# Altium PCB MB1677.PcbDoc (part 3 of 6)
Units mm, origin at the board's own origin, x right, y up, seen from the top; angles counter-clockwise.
Board outline 78 x 105 mm, 6 copper layers (Top Layer, Signal Layer 1, Signal Layer 2, Signal Layer 3, Signal Layer 4, Bottom Layer), stack 1.574 mm thick; 404 components, 325 nets, 1691 pads, 961 vias.
Unrouted connection lines stored in the file: 9.
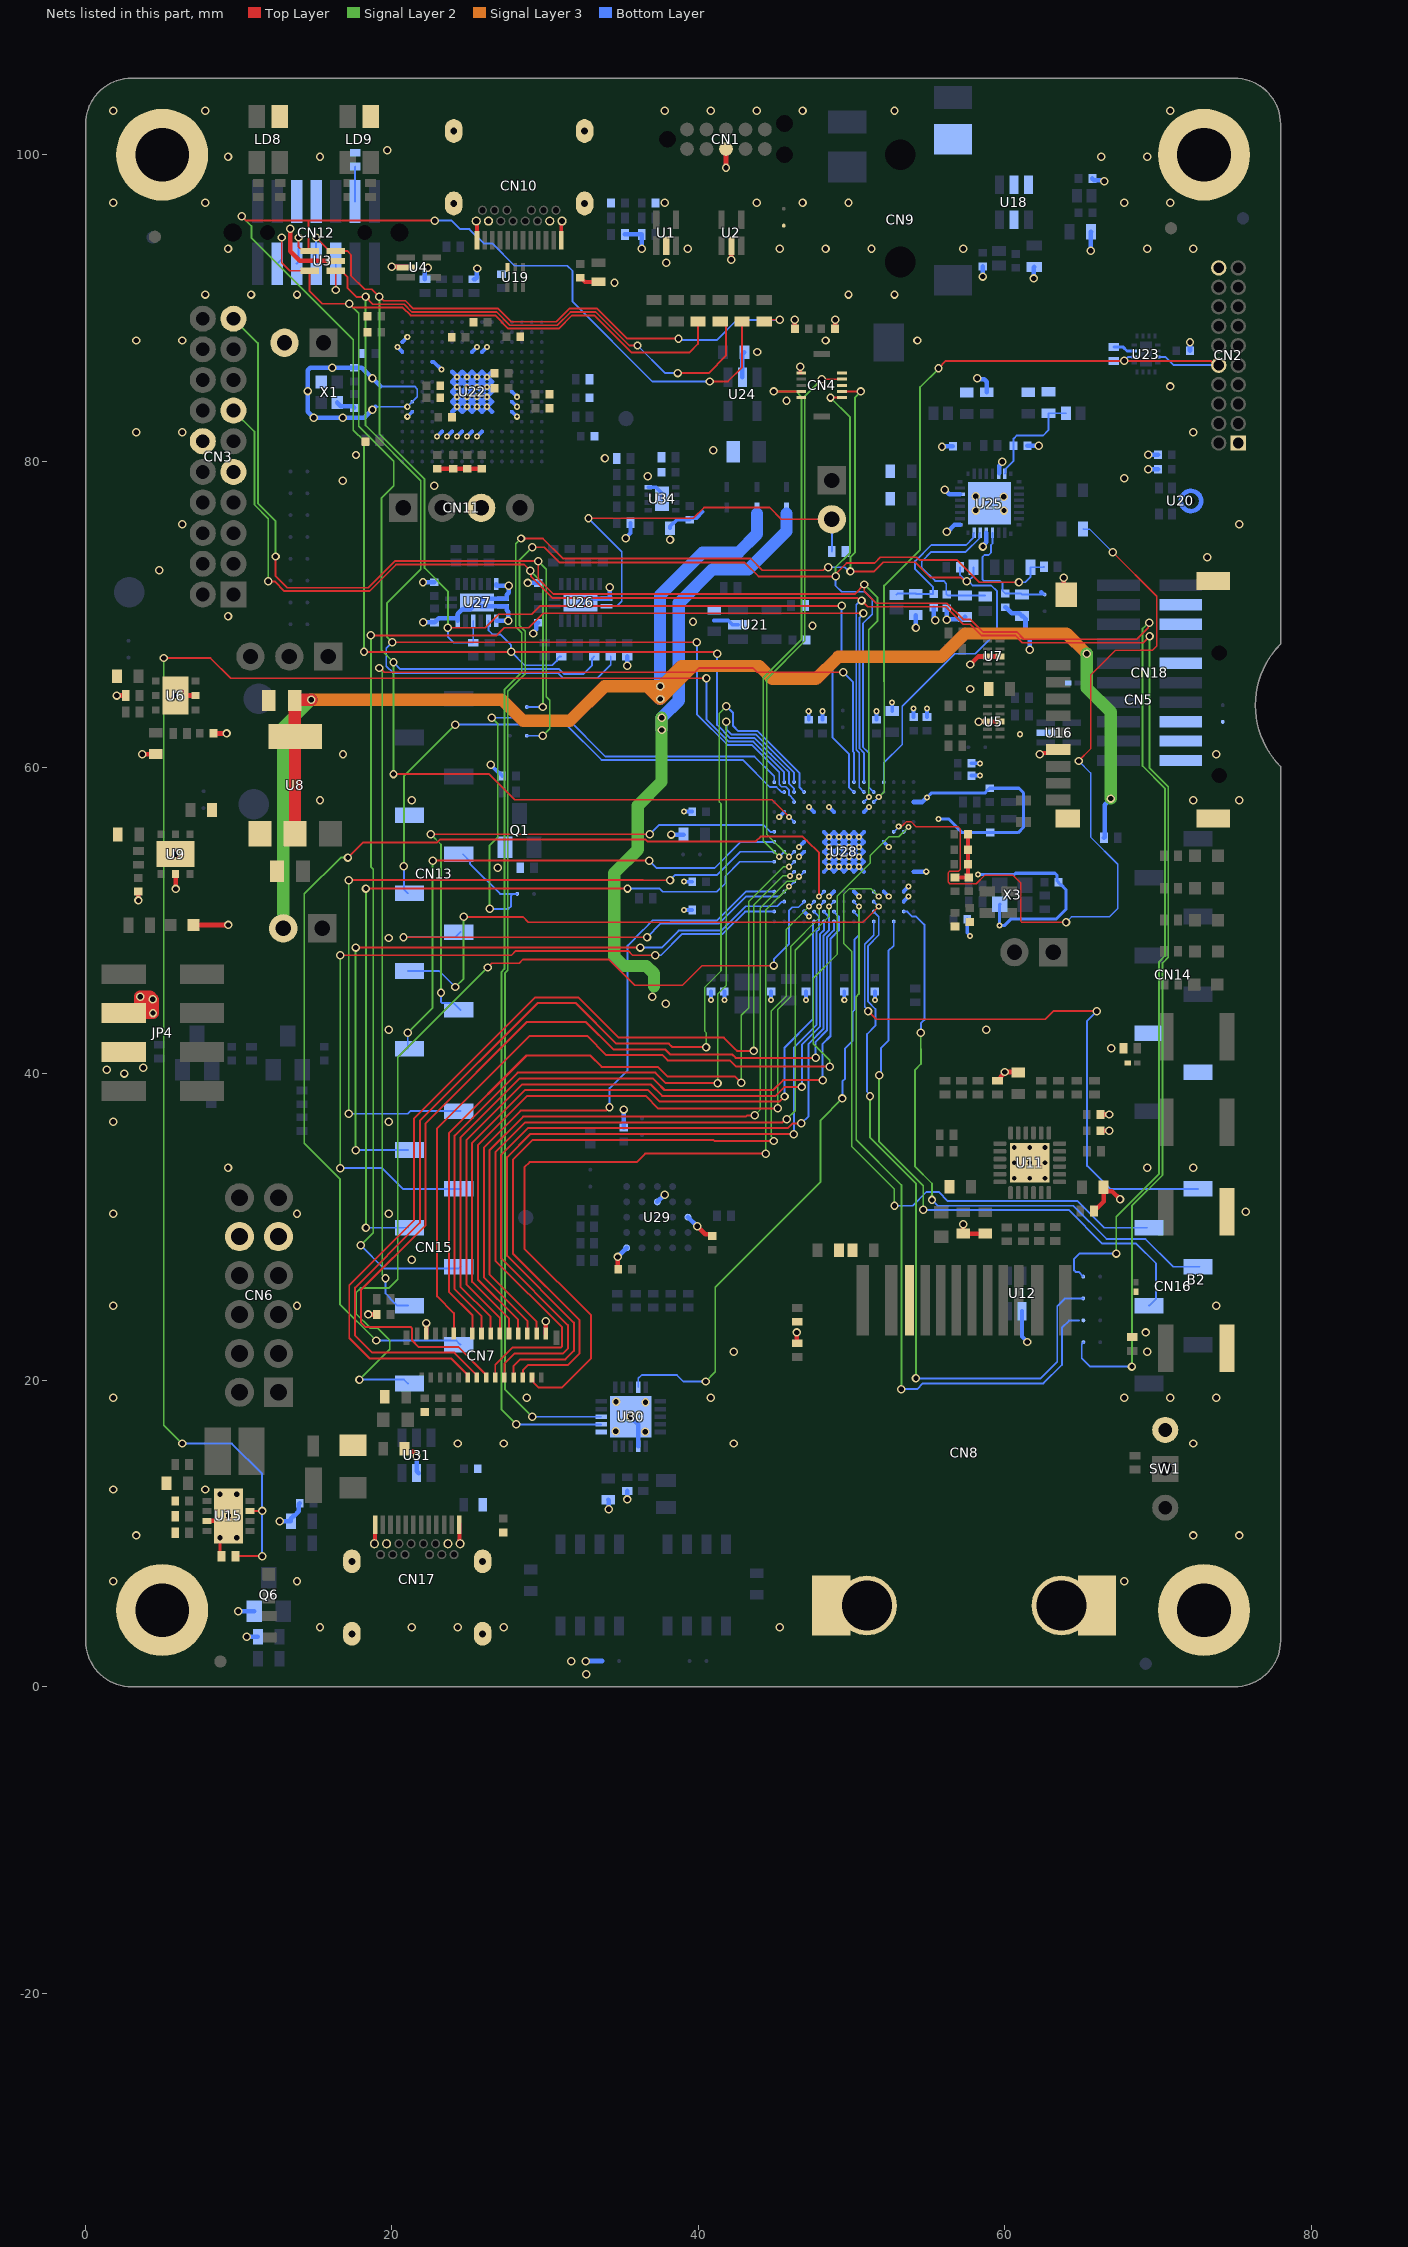
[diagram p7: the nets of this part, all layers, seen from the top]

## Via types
v1: diameter 0.55, hole 0.35, Top Layer to Bottom Layer, tented both sides, 748 vias
v2: diameter 0.4, hole 0.2, Top Layer to Bottom Layer, tented both sides, 203 vias
v3: diameter 0.6, hole 0.3, Top Layer to Bottom Layer, tented both sides, 9 vias
v4: diameter 0.55, hole 0.33, Top Layer to Bottom Layer, tented both sides, 1 vias

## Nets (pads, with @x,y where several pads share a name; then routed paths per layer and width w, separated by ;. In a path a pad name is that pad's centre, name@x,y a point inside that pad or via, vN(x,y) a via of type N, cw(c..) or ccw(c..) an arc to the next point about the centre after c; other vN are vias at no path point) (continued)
5V_UCPD: D4.1 JP4.3 SB29.1 | length 47.8
  Top Layer w0.8: JP4.3@2.5,43.965 JP4.3@2.51,43.975 ; JP4.3@2.51,43.975 JP4.3@3.31,43.975 ; JP4.3@2.51,43.975 2.75,44.215 JP4.3@3.55,44.215 ; JP4.3@3.31,43.975 v1(4.4,43.975) 4.4,44.85 v1(4.375,44.875) ; JP4.3@3.31,43.975 JP4.3@3.55,44.215 ; JP4.3@3.55,44.215 3.715,44.215 v1(4.375,44.875) ; JP4.3@3.55,44.215 3.55,45.015 3.575,45.04 v1(3.575,45.05) 4.2,45.05 v1(4.375,44.875)
  Signal Layer 2 w0.8: 37.1,45.725 37.1,46.55 36.6,47.05 35.125,47.05 34.5,47.675 34.5,53.1 36.05,54.65 36.05,57.525 37.6,59.075 v1(37.6,62.45) v1(37.6,63.25)
  Bottom Layer w0.3: v1(32.65,1.675) 32.655,1.68 SB29.1@33.725,1.68
  Bottom Layer w0.8: v1(37.6,62.45) v1(37.6,63.25) 38.725,64.375 38.725,70.75 40.9,72.925 43.25,72.925 45.75,75.425 45.75,76.58
  other v1: 32.675,0.825 31.7,1.675 37.875,44.575 37,45.05
5V_VIN: C24.2 D3.1 JP3.2 JP4.5 R90.2 U8.2 U8.4 | length 114.3
  Top Layer w0.8: U8.2@13.675,55.675 U8.4@13.675,62.025 13.65,62.05 C24.2@13.65,64.375 13.7,64.425 v1(14.725,64.425)
  Signal Layer 2 w0.8: JP3.2@12.905,49.5 12.905,62.605 v1(14.725,64.425) ; v1(65.35,67.425) 65.35,65.2 66.925,63.625 v1(66.925,57.975)
  Signal Layer 3 w0.8: v1(14.725,64.425) 27.175,64.425 28.55,63.05 31.625,63.05 33.875,65.3 36.675,65.3 ; v1(65.35,67.425) 64.025,68.75 57.4,68.75 55.875,67.225 49.125,67.225 47.675,65.775 44.825,65.775 44.3,66.3 43.975,66.625 39.65,66.625 ; 36.675,65.3 v1(37.5,65.3) ; 36.675,65.3 v1(37.5,64.475) ; v1(37.5,64.475) v1(37.5,65.3) ; v1(37.5,64.475) 39.65,66.625 ; v1(37.5,65.3) 37.575,65.3 38.9,66.625 39.65,66.625
  Bottom Layer w0.3: R90.2@66.475,55.41 66.513,55.448 66.513,57.563 v1(66.925,57.975)
  Bottom Layer w0.8: v1(37.5,64.475) v1(37.5,65.3) 37.5,71.25 40.275,74.025 42.6,74.025 43.825,75.25 43.825,76.58
  other v1: 2.525,40.025 1.375,40.275 3.775,40.4
ARD_A0: CN16.6 U28.R5 | length 39.8
  Top Layer w0.12: v1(51.075,44.1) 51.6,43.575 62.65,43.575 63.175,44.1 v1(66,44.1)
  Bottom Layer w0.12: v1(51.075,44.1) 51.075,44.164 50.855,44.384 50.855,48.462 51.45,49.057 U28.R5@51.45,49.95 ; v1(66,44.1) 65.375,43.475 65.375,34 66.88,32.495 CN16.6@72.615,32.495
ARD_A1: CN16.5 U28.M5 | length 42.7
  Signal Layer 2 w0.1: v2(51.775,51.575) 51.25,52.1 49.855,52.1 49.475,51.72 49.475,51.625 49.475,48.525 50.025,47.975 50.025,35.25 52.8,32.475 v1(52.8,31.4)
  Bottom Layer w0.12: v1(52.8,31.4) 53.991,31.4 54.891,32.3 55.675,32.3 56.275,31.7 64.76,31.7 66.505,29.955 CN16.5@69.298,29.955
  Bottom Layer w0.13: U28.M5@51.45,51.9 v2(51.775,51.575)
ARD_A2: CN16.4 U28.P2 | length 39.7
  Signal Layer 2 w0.1: 54.525,41.625 v1(54.525,42.7)
  Signal Layer 2 w0.12: 54.525,41.625 54.525,40.65 54.15,40.275 54.15,33.95 55.25,32.85 v1(55.25,31.775)
  Bottom Layer w0.12: U28.P2@53.4,50.6 53.647,50.6 53.972,50.275 54.225,50.275 54.75,49.75 54.75,43.525 54.525,43.3 v1(54.525,42.7) ; v1(55.25,31.775) 55.625,31.4 64.47,31.4 66.645,29.225 69.175,29.225 70.985,27.415 CN16.4@72.727,27.415
ARD_A3: CN16.3 U28.R3 | length 40
  Signal Layer 2 w0.12: v1(51.8,39.925) 51.8,35.575 54.675,32.7 v1(54.675,31.125)
  Bottom Layer w0.12: v1(51.8,39.925) 51.925,40.05 51.925,41.7 52.405,42.18 52.405,48.033 52.75,48.378 U28.R3@52.75,49.95 ; v1(54.675,31.125) 64.175,31.125 66.375,28.925 68.575,28.925 69.875,27.625 69.875,25.325 69.425,24.875 CN16.3@69.41,24.875
ARD_A4: SB24.1 U28.P5 | length 47.9
  Signal Layer 2 w0.12: v1(51.2,38.55) 51.2,35.864 54.2,32.864 v1(54.2,20.125)
  Bottom Layer w0.12: v1(51.2,38.55) 51.2,38.64 51.005,38.835 51.005,42.605 51.55,43.15 51.55,44.24 51.075,44.715 51.075,48.371 51.775,49.071 51.775,50.275 U28.P5@51.45,50.6 ; v1(54.2,20.125) 62.35,20.125 63.425,21.2 63.425,24.825 63.95,25.35 SB24.1@65.125,25.35
ARD_A5: SB23.1 U28.N7 | length 48.1
  Signal Layer 2 w0.12: v2(50.475,50.925) 50.475,45.225 50.3,45.05 50.3,35.7 53.25,32.75 v1(53.25,19.425)
  Bottom Layer w0.12: v1(53.25,19.425) 54.275,19.425 54.65,19.8 62.525,19.8 63.725,21 63.725,23.425 64.2,23.9 64.85,23.9
  Bottom Layer w0.13: U28.N7@50.15,51.25 v2(50.475,50.925)
ARD_D0: CN15.1 U28.N12 | length 62.2
  Top Layer w0.1: 36.4,45.79 38.965,45.79 40.25,47.075 v1(44.925,47.075)
  Top Layer w0.12: v1(26.25,46.95) 26.525,47.225 28.3,47.225 28.55,47.475 34.15,47.475 35.835,45.79 36.4,45.79
  Signal Layer 2 w0.12: v1(17.875,20.05) 19.85,22.025 19.85,22.625 19.05,23.425 18.575,23.425 17.65,24.35 17.65,25.725 17.95,26.025 19.8,26.025 20.375,26.6 20.375,41.075 v1(26.25,46.95)
  Bottom Layer w0.12: v1(17.875,20.05) 20.783,20.05 CN15.1@21.038,19.795 ; v1(44.925,47.075) 44.925,47.5 45.925,48.5 45.925,50.678 46.132,50.885 46.535,50.885 U28.N12@46.9,51.25
ARD_D1: CN15.2 U28.M10 | length 75.7
  Top Layer w0.13: v1(17.125,54.125) 18.1,55.1 22.925,55.1 23.125,55.3 36.55,55.3 36.675,55.175 43.75,55.175 44.07,55.495 46.805,55.495 47.075,55.225 47.875,54.425 v2(47.875,51.575)
  Signal Layer 2 w0.12: v1(17.125,54.125) 16.65,54.125 14.275,51.75 14.275,35.475 16.6,33.15 16.6,24.975 v1(18.975,22.6)
  Bottom Layer w0.12: v1(18.975,22.6) 24.202,22.6 CN15.2@24.467,22.335
  Bottom Layer w0.13: v2(47.875,51.575) U28.M10@48.2,51.9
ARD_D2: CN15.3 U28.A7 | length 80.9
  Top Layer w0.12: v1(19.175,66.5) 19.22,66.5 19.256,66.464 19.505,66.215 39.76,66.215 40.045,66.5 43.55,66.5 43.825,66.225 v1(49.45,66.225)
  Signal Layer 2 w0.12: v1(19.175,66.5) 19.365,66.31 19.365,26.885 v1(19.575,26.675)
  Bottom Layer w0.12: v1(19.575,26.675) 19.575,25.675 19.891,25.359 19.891,25.323 20.339,24.875 CN15.3@21.038,24.875 ; v1(49.45,66.225) 50.085,65.59 50.085,61.059 50.15,60.994 50.15,60.575 U28.A7@50.15,59.05
ARD_D3: CN15.4 U28.A6 | length 91.4
  Top Layer w0.12: v1(18.625,68.625) 26.825,68.625 27.325,69.125 28.925,69.125 29.875,70.075 v1(50.775,70.075)
  Signal Layer 2 w0.12: v1(17.958,28.808) 18.775,29.625 18.775,53.375 18.625,53.525 v1(18.625,68.625)
  Bottom Layer w0.12: v1(17.958,28.808) 19.465,27.3 24.352,27.3 CN15.4@24.467,27.415 ; v1(50.775,70.075) 50.775,70.04 50.525,69.79 50.525,65.625 50.525,61.242 50.8,60.967 U28.A6@50.8,59.05
ARD_D4: CN15.5 U28.J15 | length 52.7
  Top Layer w0.12: v1(18.3,52.1) v1(35.375,52.1)
  Signal Layer 2 w0.12: v1(18.3,29.95) v1(18.3,52.1)
  Bottom Layer w0.12: v1(18.3,29.95) 18.305,29.955 CN15.5@21.038,29.955 ; v1(35.375,52.1) 37.465,52.1 37.675,51.89 41.21,51.89 41.77,52.45 41.77,52.907 42.713,53.85 43.05,53.85 U28.J15@44.95,53.85
ARD_D5: CN15.6 U28.P15 | length 52
  Top Layer w0.12: v1(16.625,47.75) 27.8,47.75 28.08,48.03 35.42,48.03 35.7,47.75 v1(37.175,47.75)
  Signal Layer 2 w0.12: v1(16.625,33.85) v1(16.625,47.75)
  Bottom Layer w0.12: v1(16.625,33.85) 19.35,33.85 20.705,32.495 CN15.6@24.467,32.495 ; v1(37.175,47.75) 37.56,47.75 38.95,49.14 41.592,49.14 43.052,50.6 U28.P15@44.95,50.6
ARD_D6: CN15.7 U28.N14 | length 45.9
  Top Layer w0.12: v1(17.625,48.25) v1(36.2,48.25)
  Signal Layer 2 w0.12: v1(17.625,35.025) v1(17.625,48.25)
  Bottom Layer w0.12: v1(17.625,35.025) 21.028,35.025 CN15.7@21.038,35.035 ; v1(36.2,48.25) 37.6,48.25 38.71,49.36 41.5,49.36 43.09,50.95 45.15,50.95 45.429,51.229 45.579,51.229 U28.N14@45.6,51.25
ARD_D7: CN15.8 U28.H15 | length 51.2
  Top Layer w0.1: 36.4,52.65 v1(38.15,52.65)
  Top Layer w0.12: v1(17.175,52.65) 36.4,52.65
  Signal Layer 2 w0.12: v1(17.175,37.4) v1(17.175,52.65)
  Bottom Layer w0.12: v1(17.175,37.4) 21.025,37.4 21.2,37.575 CN15.8@24.466,37.575 ; v1(38.15,52.65) 38.495,52.995 41.235,52.995 42.74,54.5 U28.H15@44.95,54.5
ARD_D8: CN13.1 U28.G15 | length 36.2
  Top Layer w0.12: v1(22.65,53.925) v1(36.8,53.925)
  Signal Layer 2 w0.12: v1(21.025,42.7) 22.65,44.325 v1(22.65,53.925)
  Bottom Layer w0.12: v1(21.025,42.7) 21.025,41.652 CN13.1@21.038,41.639 ; v1(36.8,53.925) 37.29,53.435 41.053,53.435 42.768,55.15 43.2,55.15 U28.G15@44.95,55.15
ARD_D9: CN13.2 U28.F15 | length 35.6
  Top Layer w0.12: v1(22.525,55.65) v1(36.825,55.65)
  Signal Layer 2 w0.12: v1(22.525,55.65) 23.2,54.975 v1(23.2,45.3)
  Bottom Layer w0.12: v1(23.2,45.3) 23.2,44.7 23.273,44.627 24.019,44.627 CN13.2@24.467,44.179 ; v1(36.825,55.65) 37.42,56.245 44.255,56.245 44.7,55.8 U28.F15@44.95,55.8
ARD_D10: CN13.3 U28.N5 | length 36.5
  Top Layer w0.1: 36.4,49.9 50.75,49.9 v2(51.775,50.925)
  Top Layer w0.12: v1(24.675,50.25) 28.55,50.25 28.9,49.9 36.4,49.9
  Signal Layer 2 w0.12: v1(24.125,45.675) 24.675,46.225 v1(24.675,50.25)
  Bottom Layer w0.12: CN13.3@21.038,46.719 23.081,46.719 v1(24.125,45.675)
  Bottom Layer w0.13: U28.N5@51.45,51.25 v2(51.775,50.925)
ARD_D11: CN13.4 U28.M14 | length 29.9
  Top Layer w0.1: v1@36.4,48.925 v1(36.65,48.925)
  Top Layer w0.12: v1(20.75,48.925) v1@36.4,48.925
  Bottom Layer w0.12: v1(20.75,48.925) 24.133,48.925 CN13.4@24.467,49.259 ; v1(36.65,48.925) 37.525,49.8 41.318,49.8 43.093,51.575 45.275,51.575 U28.M14@45.6,51.9
ARD_D12: CN13.5 U28.B14 | length 35.8
  Signal Layer 2 w0.12: v1(20.775,53.55) 20.775,59.442 v1(24.133,62.8)
  Bottom Layer w0.12: v1(20.775,53.55) 20.775,52.062 CN13.5@21.038,51.799 ; v1(24.133,62.8) 31.375,62.8 33.675,60.5 42.9,60.5 44.675,58.725 45.1,58.725 45.417,58.408 45.592,58.408 U28.B14@45.6,58.4
ARD_D13: CN13.6 SB15.1 U28.A15 | length 40.3
  Signal Layer 2 w0.12: v1(26.375,50.775) 26.375,54.925 26.9,55.45 26.9,62.85 v1(26.5,63.25)
  Bottom Layer w0.12: CN13.6@24.637,54.339 25.085,53.891 25.085,53.721 27.056,51.75 27.9,51.75 ; v1(26.375,50.775) 27.6,50.775 27.775,50.95 27.775,51.625 27.9,51.75 ; v1(26.5,63.25) 31.395,63.25 33.925,60.72 43.655,60.72 44.95,59.425 U28.A15@44.95,59.05 ; SB15.1@28.175,51.75 27.9,51.75
Audio_INT: R57.1 U28.F3 | length 55
  Top Layer w0.1: v2(53.075,56.15) 53.129,56.204 53.316,56.204 53.375,56.262 53.375,56.27 53.58,56.475 53.87,56.475 54.195,56.15 56.947,56.15 57.105,55.992 57.105,53.358 56.977,53.23 56.946,53.23 56.408,53.23 56.32,53.142 56.32,52.508 56.408,52.42 58.14,52.42 58.7,52.98 60.52,52.98 61.05,52.45 61.05,49.959 61.109,49.9 v1(64,49.9) ; v1(64.825,60.425) 64.825,60.443 65.6,61.218 65.6,66.025 67.225,67.65 69.65,67.65 69.925,67.925 69.925,71.175 v1(67.057,74.043)
  Bottom Layer w0.1: U28.F3@52.75,55.8 53.025,56.075 v2@53.05,56.1 ; v1(64,49.9) 64.35,50.25 66.825,50.25 67.375,50.8 67.375,53.693 65.6,55.468 65.6,59.65 v1(64.825,60.425) ; R57.1@65.125,75.575 65.136,75.564 65.536,75.564 v1(67.057,74.043)
AVDD: C126.2 C127.2 L8.2 U25.23 | length 7.3
  Bottom Layer w0.12: U25.23@60,79.175 60.05,79.225 60.05,79.5 60.575,80.025 60.575,81.475 60.775,81.675 62.5,81.675 62.85,82.025 C126.2@62.85,83.125 L8.2@64,83.125
CPVDD: C74.2 C75.2 L7.2 U25.7 | length 9.9
  Bottom Layer w0.12: L7.2@52.925,71.275 53,71.35 C74.2@54.2,71.35 54.225,71.325 55.325,71.325 55.325,71.775 54.15,72.95 54.15,73.475 55.2,74.525 57.475,74.525 57.95,75 57.95,75.275 U25.7@58,75.325
DBVDD: C56.2 C58.2 SB1.2 U25.4 | length 8.3
  Bottom Layer w0.12: U25.4@59.2,75.325 59.2,74.625 59.1,74.525 59.1,74.025 58.95,73.875 58.675,73.875 58.55,73.75 58.55,72.264 58.62,72.193 59.674,72.193 59.85,72.018 59.85,71.535 C58.2@60.025,71.36 61.055,71.36 C56.2@61.125,71.29 ; C56.2@61.135,71.3 SB1.2@62.6,71.3
  Bottom Layer w0.3: 62.385,71.44 62.425,71.4
DCVDD: C88.2 C89.2 L6.2 U25.6 | length 10.4
  Bottom Layer w0.12: C89.2@56.2,71.3 56.181,71.319 56.181,72.003 56.006,72.178 55.447,72.178 54.575,73.05 54.575,73.45 55.2,74.075 57.45,74.075 58.35,74.975 58.35,75.275 U25.6@58.4,75.325 ; C89.2@56.275,71.225 C88.2@57.4,71.225 L6.2@58.725,71.225
DETECTn: CN2.10 R70.2 U23.3 U23.10 U28.C5 | length 54.3
  Top Layer w0.12: v1(55.675,86.075) 56.144,86.544 v1(67.794,86.544) 73.455,86.544 73.733,86.265 CN2.10@73.965,86.265
  Signal Layer 2 w0.1: v2(51.775,58.075) 52.125,58.425 52.125,65.625
  Signal Layer 2 w0.12: 52.125,65.625 52.125,71.875 54.475,74.225 54.475,84.84 55.675,86.04 v1(55.675,86.075)
  Bottom Layer w0.12: R70.2@67.116,86.544 v1(67.794,86.544) 68.044,86.794 U23.10@68.441,86.794 ; U23.3@69.991,86.794 70.506,86.794 71.035,86.265 CN2.10@73.965,86.265
  Bottom Layer w0.13: U28.C5@51.45,57.75 v2(51.775,58.075)
GND: B2.1 B2.2 C1.2 C2.2 C3.1 C4.1 C5.2 C6.2 C7.2 C8.2 C9.2 C10.2 C11.2 C12.2 C13.2 C14.2 C15.2 C16.2 C17.2 C18.2 C19.2 C20.2 C21.2 C22.1 C23.2 C24.1 C25.2 C26.1 C27.1 C28.1 C29.2 C30.2 C31.2 C32.1 C33.1 C34.1 C35.1 C36.1 C37.1 C38.1 C39.1 C40.2 C41.1 C42.1 C43.1 C44.1 C45.1 C46.1 C47.1 C48.2 C49.1 C50.2 C51.1 C52.1 C53.1 C54.2 C55.1 C56.1 C57.2 C58.1 C59.1 C60.1 C61.1 C62.2 C63.1 C64.1 C65.1 C66.1 C67.1 C68.1 C69.1 C70.1 C71.1 C72.2 C73.1 C74.1 C75.1 C77.1 C78.1 C79.2 C80.1 C81.1 C83.1 C84.1 C88.1 C89.1 C90.1 C91.2 C92.1 C93.2 C94.1 C95.2 C96.1 C97.2 C98.2 C99.2 C100.1 C101.1 C102.1 C103.2 C104.1 C105.1 C106.2 C107.1 C108.2 C109.1 C110.2 C111.2 C112.2 C113.1 C114.1 C115.1 C116.2 C119.1 C120.1 C121.2 C122.1 C123.1 C126.1 C127.1 C128.1 C129.1 CN1.3 CN2.1 CN2.20 CN3.5 CN3.16 CN4.1 CN4.3 CN4.6 CN4.10 CN5.6 CN5.10 CN5.11 CN5.12 CN5.13 CN6.5 CN6.11 CN7.1 CN7.27 CN8.10 CN8.13 CN8.14 CN9.3 CN10.A1 CN10.A12 CN10.B1 CN10.B12 CN10.SH1 CN10.SH2 CN10.SH3 CN10.SH4 CN11.3 CN12.5 CN12.7 CN13.7 CN14.2 CN14.3 CN17.A1 CN17.A12 CN17.B1 CN17.B12 CN17.SH1 CN17.SH2 CN17.SH3 CN17.SH4 CN18.3 CN18.5 CN18.9 CN18.15 CN18.17 CN18.19 H1.1 H2.1 H3.1 H4.1 JP5.2 LD5.2 LD8.3 LD9.3 Q1.2 Q6.2 R14.1 R29.2 R36.1 R40.2 R45.2 R48.2 R50.1 R51.1 R52.1 R53.1 R54.1 R55.1 R58.1 R65.2 R67.2 R70.1 R71.2 R74.1 R77.1 R79.1 R91.1 R123.2 R124.1 R126.2 R129.2 R132.1 R133.1 R137.1 R139.1 SB17.1 SB18.1 SW1.3 U1.2 U2.2 U3.2 U4.2 U5.3 U5.8 U6.2 U6.EP U7.3 U7.8 U8.1 U9.2 U9.EP U10.2 U11.EP U12.2 U13.2 U14.2 U15.3 U15.9 U16.2 U17.2 U18.2 U18.3 U18.5 U19.3 U20.3 U21.2 U22.D5 U22.D6 U22.D7 U22.D8 U22.D9 U22.F2 U22.F6 U22.F7 U22.F8 U22.F9 U22.F10 U22.F12 U22.G2 U22.G6 U22.G7 U22.G8 U22.G9 U22.G10 U22.G12 U22.H6 U22.H7 U22.H8 U22.H9 U22.H10 U22.H12 U22.J6 U22.J7 U22.J8 U22.J9 U22.J10 U22.K6 U22.K7 U22.K8 U22.K9 U22.K10 U22.L4 U22.M1 U22.M8 U22.M9 U22.N1 U23.11 U24.2 U25.5 U25.9 U25.14 U25.22 U25.33 U26.8 U26.17 U27.7 U27.8 U27.9 U27.10 U27.15 U27.17 U28.C1 U28.D6 U28.D9 U28.D11 U28.D14 U28.F6 U28.F7 U28.F8 U28.F9 U28.F10 U28.G4 U28.G6 U28.G7 U28.G8 U28.G9 U28.G10 U28.G12 U28.H6 U28.H7 U28.H8 U28.H9 U28.H10 U28.H12 U28.J6 U28.J7 U28.J8 U28.J9 U28.J10 U28.K1 U28.K6 U28.K7 U28.K8 U28.K9 U28.K10 U28.M2 U28.M4 U28.M7 U28.M9 U28.N2 U28.P12 U29.B3 U29.C1 U29.E5 U30.12 U30.16 U30.21 U31.2 U32.2 U34.8 U34.9 X1.2 X1.4 X3.2 | length 253.9
  Top Layer w0.2: v1(8.775,9.725) 8.775,8.625 R55.1@8.875,8.525 ; v1(46.65,86.15) 46.65,85.75 CN4.10@46.725,85.75
  Top Layer w0.25: CN17.B12@18.85,9.335 18.9,9.385 CN17.A1@18.9,10.585 ; CN17.A12@24.4,10.585 24.4,9.385 CN17.B1@24.45,9.335 ; CN10.B1@25.5,95.67 25.55,95.62 CN10.A12@25.55,94.42 ; CN10.A1@31.05,94.42 31.05,95.62 CN10.B12@31.1,95.67 ; C57.2@32.3,91.975 32.325,91.975 32.6,91.7 U13.2@33.475,91.7 ; C55.1@56.75,52.825 C33.1@57.65,52.825 57.6,52.875 C31.2@57.6,53.7 C30.2@57.6,54.625 C29.2@57.6,55.65 ; v1(58.3,63) U5.8@59.685,63 U5.3@58.865,63 ; v1(62.275,60.875) 62.356,60.875 62.431,60.95 63.275,60.95 CN5.6@63.5,61.175
  Top Layer w0.3: v1(2.025,64.7) R14.1@2.625,64.7 ; v1(3.45,51.325) C34.1@3.45,51.9 ; v1(3.7,60.875) C25.2@4.575,60.875 ; v1(5.875,52.075) U9.2@5.875,53.05 ; v1(5.875,64.7) U6.2@7.175,64.7 ; LD5.2@7.048,49.725 v1(9.3,49.725) v1@9.325,49.75 ; U15.3@7.925,10.825 9,10.825 v1(9.325,11.15) ; C26.1@8.35,62.225 v1(9.2,62.225) ; v1(13.35,95.175) 13.35,93.7 13.975,93.075 U3.2@16.325,93.075 ; v1(18.45,24.3) C48.2@19,24.3 ; v1(19.976,92.68) 20.995,92.68 U4.2@21.025,92.65 ; C52.1@20.825,15.525 20.994,15.356 21.419,15.356 21.625,15.15 v1(21.625,15.05) ; CN7.27@22.24,23.05 v1(22.24,23.74) ; C16.2@22.95,79.5 C17.2@24,79.5 C18.2@24.925,79.5 C19.2@25.85,79.5 ; CN7.1@30.04,23.05 v1(30.04,23.86) ; v1(34.725,28.055) 34.725,27.3 C47.1@34.775,27.25 ; v1(39.915,30.055) 40.44,29.53 40.795,29.53 C44.1@40.9,29.425 ; v1(41.8,99.15) CN1.3@41.8,100.38 ; v1(42.15,93.15) U2.2@42.15,94.05 ; C3.1@46.3,88.65 v1(46.3,89.225) ; v1(46.425,23.125) 46.425,22.45 R54.1@46.45,22.425 ; C4.1@48.925,88.65 v1(48.925,89.225) ; v1(57.3,30.2) C42.1@57.3,29.575 C43.1@58.725,29.575 ; v1(57.75,66.725) 58.275,67.25 U7.3@58.865,67.25 U7.8@59.685,67.25 ; R29.2@59.525,39.55 59.62,39.55 59.725,39.655 59.725,39.824 60,40.099 v1(60,40.125) 60.7,40.125 60.8,40.025 C37.1@60.875,40.1 ; v1(63.85,72.4) 63.85,71.425 CN5.13@64,71.275 ; R40.2@65.825,31.05 65.825,31.145 65.93,31.25 66.025,31.25 66.45,31.675 C41.1@66.45,32.519 ; C39.1@66.25,36.3 v1(66.825,36.3) ; C38.1@66.25,37.35 v1(66.825,37.35) ; C41.1@66.45,32.6 C41.1@66.45,32.519 ; v1(67.525,31.825) 67.001,32.349 66.62,32.349 C41.1@66.45,32.519
  Bottom Layer w0.12: 18.925,83.55 v2(21,83.55) U22.G2@21.325,83.875 21.65,84.2 21.65,84.7 21.473,84.877 19.248,84.877
  Bottom Layer w0.2: v2(54.925,58.05) 55.225,58.35 58.725,58.35 58.845,58.47 58.845,58.495 59,58.65 C102.1@59.025,58.65 60.925,58.65 61.225,58.35 61.225,56.1 60.875,55.75 C104.1@59.05,55.75 57.225,55.75 56.325,56.65 v2(55.675,56.65) ; v2(58.25,53.025) 60.625,53.025 60.7,53.1 63.281,53.1 63.399,52.983 63.399,52.626 C107.1@63.5,52.525 63.5,52.5 63.655,52.345 63.68,52.345 64,52.025 64,50.75 63.375,50.125 60.425,50.125 60,49.7 v2(59.65,49.7) 59.65,51.05 X3.2@59.675,51.075 ; R70.1@67.116,87.444 67.731,87.444 67.981,87.194 U23.11@68.441,87.194
  Bottom Layer w0.25: v2(20.35,87.45) U22.M1@20.675,87.125 ; U22.N1@20.675,87.775 v2(21,88.1) ; v2(21,82.9) U22.F2@21.325,83.225 ; U22.L4@22.625,86.475 22.725,86.475 v2(23.225,85.975) ; v2(22.95,81.6) U22.D5@23.275,81.925 ; v2(23.6,81.6) U22.D6@23.925,81.925 ; v2(24.25,81.6) U22.D7@24.575,81.925 ; v2(24.9,81.6) U22.D8@25.225,81.925 ; U22.M8@25.225,87.125 v2(25.55,87.45) ; v2(25.55,81.6) U22.D9@25.875,81.925 ; U22.M9@25.875,87.125 v2(26.2,87.45) ; v1(26.45,60.175) 27.02,59.605 27.07,59.605 27.2,59.475 C110.2@27.2,59.45 ; U22.F12@27.825,83.225 v2(28.15,82.9) ; U22.G12@27.825,83.875 v2(28.15,83.55) ; U22.H12@27.825,84.525 v2(28.15,84.2) ; v1(35.25,74.975) 35.575,75.3 R74.1@35.575,75.975 ; U34.8@36.725,78.3 36.727,78.298 37.227,78.298 37.625,77.9 U34.9@37.625,77.55 ; C64.1@38.15,75.625 38.15,75.75 38.345,75.945 38.37,75.945 38.6,76.175 C65.1@39.425,76.175 39.545,76.295 39.87,76.295 40.275,76.7 ; v2(39.05,50.7) C108.2@39.6,50.7 ; v2(39.05,52.55) C106.2@39.6,52.55 ; v2(39.05,57.125) C103.2@39.6,57.125 ; v2(40.825,44.825) C116.2@40.825,45.375 ; 41.025,69.6 41.95,69.6 42.225,69.325 U21.2@42.575,69.325 ; v2(41.7,44.825) C115.1@41.7,45.375 ; v2(44.75,44.825) C114.1@44.75,45.375 ; v2(45.275,56.775) U28.D14@45.6,57.1 ; v2(46.575,54.175) U28.H12@46.9,54.5 ; v2(46.575,54.825) U28.G12@46.9,55.15 ; U28.P12@46.9,50.6 v2(47.225,50.275) ; v2(47.025,44.825) C113.1@47.025,45.375 ; C99.2@47.2,63.125 v2(47.2,63.675) ; v2(47.225,57.425) U28.D11@47.55,57.1 ; C98.2@48.1,63.125 v2(48.1,63.675) ; U28.K10@48.2,53.2 v2(48.525,53.525) ; U28.F10@48.2,55.8 v2(48.525,55.475) ; v2(48.525,51.575) U28.M9@48.85,51.9 ; v2(48.525,57.425) U28.D9@48.85,57.1 ; v2(49.525,44.825) C112.2@49.525,45.375 ; U28.M7@50.15,51.9 v2(50.475,51.575) ; U28.K6@50.8,53.2 v2(50.475,53.525) ; U28.F6@50.8,55.8 v2(50.475,55.475) ; U28.D6@50.8,57.1 v2(51.125,57.425) ; v2(51.525,44.825) C111.2@51.525,45.375 ; C97.2@51.625,63.125 v2(51.625,63.675) ; U28.M4@52.1,51.9 v2(52.425,51.575) ; U28.G4@52.1,55.15 v2(52.425,54.825) ; C94.1@52.65,63.7 v2(52.65,64.25) ; U28.N2@53.4,51.25 v2(53.725,51.575) ; U28.M2@53.4,51.9 v2(53.725,52.225) ; C96.1@54.05,63.3 v2(54.05,63.85) ; C95.2@54.925,63.3 v2(54.925,63.85) ; C109.1@57.55,50.1 57.55,49.216 57.725,49.041 v2(57.725,49) ; C101.1@57.825,59.475 v2(58.375,59.475) ; C100.1@57.825,60.275 v2(58.375,60.275) ; U12.2@61.125,24.52 61.125,22.85 v1(61.475,22.5) ; v2(48.525,53.525) U28.K9@48.85,53.2 v2(49.175,53.525) ; v2(48.525,53.525) U28.J10@48.2,53.85 v2(48.525,54.175) ; v2(48.525,53.525) U28.J9@48.85,53.85 ; v2(48.525,54.175) U28.J9@48.85,53.85 ; v2(48.525,54.175) U28.H10@48.2,54.5 v2(48.525,54.825) ; v2(48.525,54.175) U28.H9@48.85,54.5 ; v2(48.525,54.825) U28.H9@48.85,54.5 ; v2(48.525,54.825) U28.G10@48.2,55.15 v2(48.525,55.475) ; v2(48.525,54.825) U28.G9@48.85,55.15 ; v2(48.525,55.475) U28.G9@48.85,55.15 ; v2(48.525,55.475) U28.F9@48.85,55.8 v2(49.175,55.475) ; U28.J9@48.85,53.85 v2(49.175,53.525) ; U28.J9@48.85,53.85 v2(49.175,54.175) ; U28.H9@48.85,54.5 v2(49.175,54.175) ; U28.H9@48.85,54.5 v2(49.175,54.825) ; U28.G9@48.85,55.15 v2(49.175,54.825) ; U28.G9@48.85,55.15 v2(49.175,55.475) ; v2(49.175,53.525) U28.K8@49.5,53.2 v2(49.825,53.525) ; v2(49.175,53.525) U28.J8@49.5,53.85 ; v2(49.175,54.175) U28.J8@49.5,53.85 ; v2(49.175,54.175) U28.H8@49.5,54.5 ; v2(49.175,54.825) U28.H8@49.5,54.5 ; v2(49.175,54.825) U28.G8@49.5,55.15 ; v2(49.175,55.475) U28.G8@49.5,55.15 ; v2(49.175,55.475) U28.F8@49.5,55.8 v2(49.825,55.475) ; U28.J8@49.5,53.85 v2(49.825,53.525) ; U28.J8@49.5,53.85 v2(49.825,54.175) ; U28.H8@49.5,54.5 v2(49.825,54.175) ; U28.H8@49.5,54.5 v2(49.825,54.825) ; U28.G8@49.5,55.15 v2(49.825,54.825) ; U28.G8@49.5,55.15 v2(49.825,55.475) ; v2(49.825,53.525) U28.K7@50.15,53.2 v2(50.475,53.525) ; v2(49.825,53.525) U28.J7@50.15,53.85 ; v2(49.825,54.175) U28.J7@50.15,53.85 ; v2(49.825,54.175) U28.H7@50.15,54.5 ; v2(49.825,54.825) U28.H7@50.15,54.5 ; v2(49.825,54.825) U28.G7@50.15,55.15 ; v2(49.825,55.475) U28.G7@50.15,55.15 ; v2(49.825,55.475) U28.F7@50.15,55.8 v2(50.475,55.475) ; U28.J7@50.15,53.85 v2(50.475,53.525) ; U28.J7@50.15,53.85 v2(50.475,54.175) ; U28.H7@50.15,54.5 v2(50.475,54.175) ; U28.H7@50.15,54.5 v2(50.475,54.825) ; U28.G7@50.15,55.15 v2(50.475,54.825) ; U28.G7@50.15,55.15 v2(50.475,55.475) ; v2(50.475,53.525) U28.J6@50.8,53.85 v2(50.475,54.175) ; v2(50.475,54.175) U28.H6@50.8,54.5 v2(50.475,54.825) ; v2(50.475,54.825) U28.G6@50.8,55.15 v2(50.475,55.475)
  Bottom Layer w0.3: v1@9.95,4.925 v1(9.955,4.92) Q6.2@11,4.92 ; v1@10.525,3.275 v1(10.53,3.27) R126.2@11.25,3.27 ; v1@12.675,10.8 v1(12.68,10.795) R124.1@13.4,10.795 13.4,10.975 13.57,11.145 13.62,11.145 13.924,11.449 13.924,11.919 C122.1@13.975,11.97 ; X1.4@16.425,83.825 16.425,83.8 16.65,83.575 17.05,83.575 17.052,83.573 17.427,83.573 C71.1@17.525,83.475 ; 18.925,83.55 18.2,82.825 v1(16.775,82.825) v1(14.9,82.825) 14.5,83.225 v1(14.5,84.575) 14.5,85.924 14.676,86.1 v1(16.1,86.1) C72.2@17.525,86.1 18.025,86.1 v1(18.725,85.4) 19.248,84.877 ; v1(21.625,15.05) 21.625,14.07 U31.2@21.75,13.945 ; v1(22.025,72.1) C90.1@22.75,72.1 ; v1(22.05,69.475) C93.2@22.775,69.475 22.8,69.475 23.06,69.735 U27.15@24.3,69.735 ; R67.2@22.15,91.875 22.15,92.425 v1(22.35,92.625) ; U22.F6@23.925,83.225 v2(24.25,83.55) ; U22.K6@23.925,85.825 v2(24.25,85.5) ; U27.15@24.3,69.575 U27.15@24.3,69.735 ; R65.2@25.35,91.875 25.417,91.875 25.522,91.98 25.522,92.454 25.575,92.507 v1(25.575,92.575) ; U22.F10@26.525,83.225 v2(26.2,83.55) ; U22.K10@26.525,85.825 v2(26.2,85.5) ; U27.10@26.8,69.575 v1(27.6,69.575) 27.6,70.175 27.5,70.275 27.5,70.525 U27.9@27.25,70.525 25.8,70.525 U27.17@25.55,70.775 ; U27.7@26.8,71.975 26.8,71.875 v1(27.625,71.875) 27.625,71.407 27.5,71.282 27.5,71.025 U27.8@27.25,71.025 25.8,71.025 U27.17@25.55,70.775 ; v1(28.85,72.05) C92.1@29.55,72.05 ; v1(29.225,68.75) 29.225,68.818 29.42,69.013 29.42,69.345 29.525,69.45 C91.2@29.55,69.45 ; U26.17@32.3,70.775 32.55,71.025 U26.8@34,71.025 34.225,71.025 v1(34.225,71.775) ; C121.2@34.125,12.2 34.15,12.175 v1(34.15,11.575) ; v1(34.725,28.055) U29.E5@35.32,28.65 ; C119.1@35.125,36.5 v1(35.125,37.675) ; R48.2@35.2,94.8 R45.2@36.3,94.8 v1(36.3,93.875) ; v1(35.35,12.225) R123.2@35.35,12.775 ; v1(35.35,66.65) R132.1@35.35,67.25 ; v1(35.575,17.625) 36.075,17.125 U30.12@36.075,15.7 ; U29.B3@37.32,31.65 37.795,32.125 v1(37.8,32.125) ; v1(38.225,55.625) C105.1@39.025,55.625 ; U29.C1@39.32,30.65 v1(39.915,30.055) ; U24.2@42.875,85.475 42.875,86.975 C66.1@43,87.1 ; U28.K1@54.05,53.2 v2(54.875,53.2) ; U28.C1@54.05,57.75 54.625,57.75 v2(54.925,58.05) ; v1(54.2,69.125) C74.1@54.2,69.95 ; C75.1@55.35,70.425 55.35,69.795 55.457,69.689 v1(55.457,69.621) ; v1@55.912,80.962 C73.1@56.612,80.962 ; v1(56.075,78.125) 56.091,78.125 56.366,77.85 U25.14@57.075,77.85 ; C89.1@56.2,70.4 v1(56.2,69.65) 56.223,69.673 57.248,69.673 C88.1@57.4,69.825 ; v1(56.2,75.4) 56.268,75.4 56.718,75.85 U25.9@57.075,75.85 ; v1(58.2,85.4) 58.248,85.352 58.649,85.352 58.825,85.176 C79.2@58.825,84.5 ; v1(58.55,92.05) C129.1@58.55,92.705 ; v1(58.575,74.425) 58.575,74.491 58.8,74.716 U25.5@58.8,75.325 ; U25.22@59.64,79.215 59.64,79.697 59.825,79.882 v1(59.825,79.95) ; C58.1@60.025,70.46 60.05,70.46 60.45,70.06 60.955,70.06 C56.1@61.125,69.89 61.185,69.89 61.355,69.72 61.355,69.12 61.625,68.85 v1(61.625,67.7) ; C127.1@61.475,81 v1(62.225,81) ; v1(61.9,91.925) 61.9,92.65 R79.1@61.925,92.675 ; v1(65.6,93.725) 65.613,93.737 65.613,94.962 R77.1@65.625,94.975 ; C128.1@65.72,98.45 65.72,98.428 65.825,98.323 66.452,98.323 v1(66.5,98.275) ; v1(69.353,79.463) C62.2@70.003,79.463 ; v1(69.353,80.413) C63.1@70.003,80.413 ; C67.1@72.091,87.194 v1(72.091,87.769) ; v2(24.25,83.55) U22.G6@23.925,83.875 v2(24.25,84.2) ; v2(24.25,83.55) U22.F7@24.575,83.225 v2(24.9,83.55) ; v2(24.25,83.55) U22.G7@24.575,83.875 ; v2(24.25,84.2) U22.H6@23.925,84.525 v2(24.25,84.85) ; v2(24.25,84.2) U22.G7@24.575,83.875 ; v2(24.25,84.2) U22.H7@24.575,84.525 ; v2(24.25,84.85) U22.J6@23.925,85.175 v2(24.25,85.5) ; v2(24.25,84.85) U22.H7@24.575,84.525 ; v2(24.25,84.85) U22.J7@24.575,85.175 ; v2(24.25,85.5) U22.J7@24.575,85.175 ; v2(24.25,85.5) U22.K7@24.575,85.825 v2(24.9,85.5) ; U27.15@24.3,69.735 24.3,70.05 24.575,70.325 25.1,70.325 U27.17@25.55,70.775 ; U22.G7@24.575,83.875 v2(24.9,83.55) ; U22.G7@24.575,83.875 v2(24.9,84.2) ; U22.H7@24.575,84.525 v2(24.9,84.2) ; U22.H7@24.575,84.525 v2(24.9,84.85) ; U22.J7@24.575,85.175 v2(24.9,84.85) ; U22.J7@24.575,85.175 v2(24.9,85.5) ; v2(24.9,83.55) U22.F8@25.225,83.225 v2(25.55,83.55) ; v2(24.9,83.55) U22.G8@25.225,83.875 ; v2(24.9,84.2) U22.G8@25.225,83.875 ; v2(24.9,84.2) U22.H8@25.225,84.525 ; v2(24.9,84.85) U22.H8@25.225,84.525 ; v2(24.9,84.85) U22.J8@25.225,85.175 ; v2(24.9,85.5) U22.J8@25.225,85.175 ; v2(24.9,85.5) U22.K8@25.225,85.825 v2(25.55,85.5) ; U22.G8@25.225,83.875 v2(25.55,83.55) ; U22.G8@25.225,83.875 v2(25.55,84.2) ; U22.H8@25.225,84.525 v2(25.55,84.2) ; U22.H8@25.225,84.525 v2(25.55,84.85) ; U22.J8@25.225,85.175 v2(25.55,84.85) ; U22.J8@25.225,85.175 v2(25.55,85.5) ; v2(25.55,83.55) U22.F9@25.875,83.225 v2(26.2,83.55) ; v2(25.55,83.55) U22.G9@25.875,83.875 ; v2(25.55,84.2) U22.G9@25.875,83.875 ; v2(25.55,84.2) U22.H9@25.875,84.525 ; v2(25.55,84.85) U22.H9@25.875,84.525 ; v2(25.55,84.85) U22.J9@25.875,85.175 ; v2(25.55,85.5) U22.J9@25.875,85.175 ; v2(25.55,85.5) U22.K9@25.875,85.825 v2(26.2,85.5) ; U22.G9@25.875,83.875 v2(26.2,83.55) ; U22.G9@25.875,83.875 v2(26.2,84.2) ; U22.H9@25.875,84.525 v2(26.2,84.2) ; U22.H9@25.875,84.525 v2(26.2,84.85) ; U22.J9@25.875,85.175 v2(26.2,84.85) ; U22.J9@25.875,85.175 v2(26.2,85.5) ; v2(26.2,83.55) U22.G10@26.525,83.875 v2(26.2,84.2) ; v2(26.2,84.2) U22.H10@26.525,84.525 v2(26.2,84.85) ; v2(26.2,84.85) U22.J10@26.525,85.175 v2(26.2,85.5)
  other v1: 15.3,3.875 21.3,3.875 24.3,3.875 27.3,3.875 45.3,3.875 1.8,6.875 13.8,6.875 67.8,6.875 9.875,9.725 3.3,9.875 72.3,9.875 75.3,9.875 8.775,12.575 9.875,12.575 1.8,12.875 7.8,12.875 24.3,15.875 27.3,15.875 42.3,15.875 72.3,15.875 36.525,16.65 34.6,16.675 36.55,18.575 34.625,18.6 1.8,18.875 28.8,18.875 40.8,18.875 67.8,18.875 70.8,18.875 73.8,18.875 42.3,21.875 69.3,21.875 69.2,23.125 1.8,24.875 13.8,24.875 73.8,24.875 21.3,27.875 1.8,30.875 13.8,30.875 19.8,30.875 75.725,31 9.3,33.875 69.3,33.875 72.3,33.875 1.8,36.875 19.8,36.875 66.95,41.675 19.8,42.875 58.8,42.875 19.8,48.875 26.9,53.45 5.875,54.35 15.3,57.875 21.3,57.875 72.3,57.875 75.3,57.875 16.8,60.875 73.8,60.875 57.75,65.125 47.45,69.25 39.65,69.525 9.3,69.875 4.8,72.875 73.225,73.725 38.15,74.875 6.3,75.875 75.3,75.875 58.1,76.775 59.95,76.775 59.925,77.675 58.1,77.7 22.75,78.4 16.775,78.725 67.8,78.875 36.7,79.025 33.9,80.2 17.65,80.4 40.975,80.7 55.9,80.95 3.3,81.875 6.3,81.875 72.3,81.875 18.725,83.35 45.75,83.95 70.8,84.875 43.85,87.125 3.3,87.875 6.3,87.875 48.3,87.875 54.3,87.875 7.8,90.875 10.8,90.875 13.8,90.875 49.8,90.875 52.8,90.875 34.525,91.65 37.9,92.95 9.3,93.875 39.3,93.875 45.3,93.875 48.3,93.875 51.3,93.875 57.3,93.875 69.3,93.875 72.3,93.875 1.8,96.875 7.8,96.875 37.8,96.875 43.8,96.875 46.8,96.875 49.8,96.875 67.8,96.875 70.8,96.875 9.3,99.875 15.3,99.875 66.3,99.875 69.3,99.875 19.7,100.3 1.8,102.875 7.8,102.875 37.8,102.875 40.8,102.875 43.8,102.875 46.8,102.875 52.8,102.875 70.8,102.875
  other v2: 61,62.175
  other v3: 60.625,33.2 61.625,33.2 62.625,33.2 60.625,34.2 61.625,34.2 62.625,34.2 60.625,35.2 61.625,35.2 62.625,35.2
GNDDetect: CN12.11 R58.2 | length 2.3
  Bottom Layer w0.12: CN12.11@17.59,96.95 17.59,99.215 R58.2@17.6,99.225
HiZ_DBG_IF_EN: JP1.2 R133.2 U26.9 | length 26.1
  Top Layer w0.12: v1(32.825,76.275) 39.675,76.275 40.375,76.975 44.65,76.975 45.423,76.202 JP1.2@48.715,76.202
  Bottom Layer w0.12: v1(32.825,76.275) 35,74.1 35,70.85 34.675,70.525 U26.9@34,70.525 ; R133.2@48.7,74.1 48.715,74.115 JP1.2@48.715,76.202
I2C1_SCL: CN3.7 SB19.2 SB21.1 U28.B6 | length 150
  Top Layer w0.12: v1(11.925,72.15) 12.35,72.15 12.979,71.521 18.532,71.521 20.266,73.255 28.62,73.255 v1(29.025,72.85) 29.064,72.811 29.064,72.486 30.475,71.075 50.365,71.075 50.54,70.9 v1(50.65,70.9) 51.05,70.5 56.139,70.5 56.609,70.03 57.289,69.35 57.75,69.35 58.475,68.625 60.675,68.625 61.15,68.15 69.025,68.15 v1(69.45,68.575)
  Signal Layer 2 w0.12: CN3.7@9.65,83.3 11.025,81.925 11.025,77.15 11.925,76.25 v1(11.925,72.15) ; v1(29.025,72.85) 29.85,72.025 v1(29.85,63.95) ; v1(68.3,20.9) 68.3,31.389 70.295,33.384 70.295,47.234 70.67,47.609 70.67,58.741 69.45,59.961 v1(69.45,68.575)
  Bottom Layer w0.12: SB19.2@28.8,63.95 v1(29.85,63.95) ; v1(50.65,70.9) 50.575,70.9 50.305,70.63 50.305,61.151 50.5,60.956 50.5,58.7 U28.B6@50.8,58.4 ; SB21.1@65.127,22.49 65.127,22.455 65.025,22.353 65.025,21.45 65.575,20.9 v1(68.3,20.9)
I2C1_SDA: CN3.10 SB16.2 SB25.1 U28.C6 | length 155.8
  Top Layer w0.12: v1(12.4,73.775) 12.4,72.5 13.159,71.741 18.441,71.741 20.175,73.475 v1(29.55,73.475) 29.55,72.311 30.541,71.32 50.195,71.32 v1(50.825,71.95) 50.825,71.5 51.6,70.725 56.225,70.725 57.277,69.673 57.752,69.673 58.575,68.85 60.775,68.85 61.25,68.375 68.625,68.375 69.361,69.111 69.361,69.386 v1(69.425,69.45)
  Signal Layer 2 w0.1: v2(51.125,58.075) 51.125,65.625
  Signal Layer 2 w0.12: CN3.10@9.65,89.3 11.245,87.705 11.245,77.241 12.4,76.086 v1(12.4,73.775) ; v1(29.55,73.475) 30.07,72.955 30.07,64.63 30.3,64.4 30.3,62.525 v1(29.85,62.075) ; v1(50.825,71.95) 51.7,71.075 51.7,69.575 51.125,69 51.125,65.625 ; v1(67.275,28.275) 67.275,30.675 70.075,33.475 70.075,47.325 70.45,47.7 70.45,58.65 68.99,60.11 68.99,69.065 69.375,69.45 v1(69.425,69.45)
  Bottom Layer w0.12: SB16.2@28.8,62.075 v1(29.85,62.075) ; SB25.1@65.125,26.775 64.825,27.075 64.625,27.075 64.525,27.175 64.525,27.925 64.875,28.275 v1(67.275,28.275)
  Bottom Layer w0.13: U28.C6@50.8,57.75 v2(51.125,58.075)
I2C4_SCL: CN4.5 R62.2 R80.1 U28.B5 U30.18 | length 129.2
  Top Layer w0.12: v1(29.15,74.375) 29.95,74.375 30.95,73.375 43.025,73.375 43.925,72.475 v1(48.975,72.475) 49.057,72.557 49.057,72.732 49.675,73.35 51.5,73.35 51.875,73.725 54.25,73.725 54.425,73.55 56.875,73.55 58.325,72.1 v1(60.925,72.1) ; v1(48.625,84.15) CN4.5@49.375,84.15
  Signal Layer 2 w0.12: v1(29.15,17.625) 27.37,19.405 27.37,46.584 27.555,46.769 27.555,64.994 28.695,66.134 28.695,68.891 28.325,69.261 28.325,73.55 v1(29.15,74.375) ; v1(48.625,84.15) 49.9,82.875 49.9,74.025 48.95,73.075 48.95,72.5 v1(48.975,72.475)
  Bottom Layer w0.12: v1(29.15,17.625) U30.18@33.65,17.625 ; v1(48.975,72.475) 48.95,72.45 48.95,71.875 49.35,71.475 50.85,71.475 51.35,70.975 51.35,70.017 50.745,69.412 50.745,61.333 51.125,60.953 51.125,58.725 U28.B5@51.45,58.4 ; v1(60.925,72.1) 61.35,72.1 61.675,72.425 R62.2@61.675,73.075 62.525,73.075 R80.1@62.55,73.1
I2C4_SDA: CN4.4 R73.2 R81.1 U28.A4 U30.17 | length 129.7
  Top Layer w0.12: v1(28.425,74.95) 29.85,74.95 31.15,73.65 43.4,73.65 44.175,72.875 48.159,72.875 48.359,73.075 v1(48.475,73.075) ; CN4.4@49.375,84.55 v1(50.6,84.55) ; v1@50.007,72.718 v1(49.925,72.8) 51.475,72.8 52.075,73.4 54.15,73.4 55.15,72.4 57.159,72.4 57.409,72.15 v1(57.525,72.15)
  Signal Layer 2 w0.12: v1(28.105,17.13) 27.15,18.085 27.15,46.675 27.335,46.86 27.335,65.085 28.475,66.225 28.475,68.8 28.075,69.2 28.075,74.6 v1(28.425,74.95) ; v1(49.925,72.8) 49.925,73.739 50.225,74.039 50.225,84.175 v1(50.6,84.55)
  Bottom Layer w0.12: v1(28.105,17.13) 28.11,17.125 U30.17@33.65,17.125 ; v1(48.475,73.075) 49.557,73.075 49.832,72.8 v1(49.925,72.8) ; U28.A4@52.1,59.05 52.1,60.3 53.305,61.505 53.305,64.005 56.725,67.425 58.075,67.425 59.5,68.85 59.5,71.5 59.117,71.883 57.902,71.883 57.635,72.15 v1@57.6,72.15 ; R81.1@57.075,73.075 57.075,72.57 57.495,72.15 v1(57.525,72.15) v1@57.6,72.15 ; R73.2@57.95,73.075 57.95,72.65 57.95,72.5 v1@57.6,72.15
IBUS_SENSE: U28.P7 U30.4 | length 40.2
  Signal Layer 2 w0.12: v1(40.475,19.925) 41.1,20.55 41.1,26.089 47.975,32.964 47.975,36.975 v1(49.4,38.4)
  Bottom Layer w0.12: U30.4@36.075,19.55 36.075,20.125 36.3,20.35 38.6,20.35 39.025,19.925 v1(40.475,19.925) ; v1(49.4,38.4) 49.4,39.525 49.575,39.7 49.575,41.675 50.075,42.175 50.075,44.065 50.185,44.175 50.185,48.761 50.475,49.051 50.475,50.275 U28.P7@50.15,50.6
JTCK: CN12.6 R8.2 R69.2 U3.4 U27.11 U28.B13 | length 120.5
  Top Layer w0.12: v1(10.2,95.975) 10.475,95.7 14.525,95.7 ; v1(13.9,94.6) 13.9,93.975 14.01,93.865 14.485,93.865 U3.4@14.55,93.8 ; U3.4@14.625,93.725 U3.4@14.55,93.8 ; v1(18.175,67.55) v1(27.775,67.55) 40.984,67.55 41.109,67.425 v1(41.225,67.425) ; v1(22.8,95.7) 14.525,95.7 ; v1(40.75,85.2) 41.925,85.2 42.85,86.125 R8.2@42.85,89.125 ; 14.525,95.7 14.55,95.675 U3.4@14.55,93.8
  Signal Layer 2 w0.12: v1(10.2,95.975) 10.825,95.35 10.825,94.575 17.475,87.925 17.475,82.025 18.175,81.325 v1(18.175,67.55)
  Bottom Layer w0.12: CN12.6@13.78,92.886 13.775,92.891 13.9,93.016 v1(13.9,94.6) ; v1(22.8,95.7) 23.9,95.7 24.455,95.145 25.055,95.145 25.985,94.215 26.532,94.215 27.997,92.75 31.45,92.75 31.788,92.412 31.788,90.413 37,85.2 v1(40.75,85.2) ; U27.11@26.3,69.575 26.3,68.95 26.56,68.69 27.06,68.69 27.775,67.975 v1(27.775,67.55) 28.65,66.675 30.475,66.675 30.76,66.96 30.76,67.055 30.955,67.25 R69.2@31.05,67.25 ; v1(41.225,67.425) 41.225,62.782 42.085,61.922 43.682,61.922 44.73,60.874 45.504,60.1 45.925,59.679 45.925,58.95 46.25,58.625 U28.B13@46.25,58.4
JTDI: CN12.10 R7.2 R78.2 U3.1 U28.C13 | length 112
  Top Layer w0.12: v1(16.325,91.172) U3.1@16.325,92.425 16.725,92.425 16.865,92.285 16.865,92.26 17.087,92.037 17.087,91.312 17.675,90.725 v1(18.275,90.725) 18.755,90.245 20.791,90.245 21.301,89.735 26.832,89.735 27.692,88.875 30.799,88.875 31.659,89.735 33.301,89.735 35.486,87.55 v1(36.025,87.55) ; v1(20.025,68.175) v1(39.9,68.175) ; v1(38.65,85.75) 40.675,85.75 41.8,86.875 41.8,88.865 41.54,89.125 R7.2@41.425,89.125
  Signal Layer 2 w0.12: v1(18.275,90.725) 18.275,82.325 21.875,78.725 21.875,72.94 19.665,70.73 19.665,68.535 v1(20.025,68.175)
  Bottom Layer w0.12: CN12.10@16.32,92.886 16.325,92.881 v1(16.325,91.172) ; v1(20.025,68.175) 19.625,67.775 19.625,66.625 20.075,66.175 30.825,66.175 31.175,65.825 33.4,65.825 34.275,66.7 R78.2@34.275,67.25 ; v1(36.025,87.55) 37.825,85.75 v1(38.65,85.75) ; v1(39.9,68.175) 39.9,63.475 41.9,61.475 43.497,61.475 45.275,59.697 45.275,58.9 45.425,58.75 45.7,58.75 45.925,58.525 45.925,58.211 46.225,57.911 46.225,57.775 U28.C13@46.25,57.75
JTDO: CN12.8 R2.1 R9.2 U3.3 U27.13 U28.B7 | length 104.5
  Top Layer w0.12: v1(15.045,94.6) 15.78,93.865 16.185,93.865 U3.3@16.325,93.725 17.075,93.725 17.325,93.475 17.325,92.111 18.211,91.225 18.675,91.225 v1(19.175,90.725) 19.199,90.725 19.459,90.465 20.882,90.465 21.392,89.955 26.923,89.955 27.783,89.095 30.708,89.095 31.568,89.955 33.392,89.955 35.347,88 v1(38.7,88) ; v1(23.65,69.125) 26.075,69.125 26.96,70.01 29.135,70.01 29.675,70.55 33,70.55 v1(49.35,70.55) ; R9.2@44.3,89.125 44.4,89.225 v1(45.3,89.225) v1@45.3,89.125
  Signal Layer 2 w0.12: v1(19.175,90.725) 19.175,81.775 22.125,78.825 22.125,73.025 23.65,71.5 v1(23.65,69.125)
  Bottom Layer w0.12: v1(15.045,94.6) 15.045,92.891 CN12.8@15.05,92.886 ; v1(23.65,69.125) 23.65,68.525 24.025,68.15 R2.1@25.3,68.15 U27.13@25.3,69.575 ; v1(38.7,88) 38.782,87.918 38.968,87.918 38.985,87.9 41.2,87.9 42.52,89.22 45.295,89.22 v1(45.3,89.225) ; v1(49.35,70.55) 49.35,67 48.765,66.415 48.765,65.625 48.765,61.959 49.825,60.899 49.825,58.725 U28.B7@50.15,58.4
JTMS: CN12.4 R6.2 R72.2 U3.5 U28.E13 | length 110.4
  Top Layer w0.1: 36.4,57.9 44.8,57.9 v2(45.925,56.775)
  Top Layer w0.12: v1(12.8,94.6) 12.8,92.95 13.325,92.425 U3.5@14.625,92.425 14.625,91.1 15.45,90.275 17.235,90.275 17.485,90.025 20.7,90.025 21.21,89.515 26.741,89.515 27.601,88.655 30.89,88.655 31.75,89.515 33.21,89.515 33.8,88.925 35.625,87.1 39.425,87.1 39.975,87.65 R6.2@39.975,89.125 ; v1(20.1,59.575) 26.35,59.575 28.025,57.9 36.4,57.9
  Signal Layer 2 w0.12: v1(17.2,90.275) 17.825,89.65 17.825,82.275 20.11,79.99 20.11,78.385 19.325,77.6 19.325,67.65 v1(20.1,66.875) v1(20.1,59.575)
  Bottom Layer w0.12: CN12.4@12.51,92.886 12.8,93.176 v1(12.8,94.6) ; v1(20.1,66.875) 20.55,66.425 30.915,66.425 31.24,66.1 32.475,66.1 33.06,66.685 33.06,67.11 R72.2@33.2,67.25
  Bottom Layer w0.13: v2(45.925,56.775) U28.E13@46.25,56.45
LCD_A0_RS: CN7.21 U28.F2 | length 62.3
  Top Layer w0.13: CN7.21@24.04,23.05 24.04,24.39 22.95,25.48 22.95,36.452 28.988,42.49 32.735,42.49 34,41.225 37.662,41.225 37.997,40.89 42.06,40.89 42.475,40.475 v1(48.575,40.475)
  Signal Layer 2 w0.1: v1(48.575,40.475) 48.575,40.9 47.5,41.975 47.5,46.25 49.05,47.8 49.05,51.6 51.225,53.775 51.225,54.25 52.45,55.475 53.075,55.475 v2(53.725,56.125)
  Bottom Layer w0.13: U28.F2@53.4,55.8 v2(53.725,56.125)
LCD_BL_CTRL: R55.2 U15.7 U28.A14 | length 111.6
  Top Layer w0.12: v1(5.1,67.15) 8.15,67.15 9.475,65.825 v1(40.525,65.825) ; R55.2@9.775,8.525 v1(11.525,8.525) ; U15.7@10.725,11.475 v1(11.525,11.475) v1@11.55,11.5
  Signal Layer 2 w0.12: v1(5.1,67.15) 5.1,17.075 v1(6.3,15.875)
  Bottom Layer w0.12: v1(6.3,15.875) 9.55,15.875 11.525,13.9 v1(11.525,11.475) v1(11.525,8.525)
  Bottom Layer w0.127: v1(40.525,65.825) 40.525,63.166 41.993,61.698 43.59,61.698 45.6,59.688 U28.A14@45.6,59.05
LCD_CTP_INT: CN4.2 U28.H13 | length 35.1
  Top Layer w0.12: v1(48.05,85.35) CN4.2@49.375,85.35
  Signal Layer 2 w0.1: 44.45,65.625 44.45,55.65 v2(45.925,54.175)
  Signal Layer 2 w0.12: 44.45,65.625 44.45,65.764 46.945,68.259 46.945,84.245 v1(48.05,85.35)
  Bottom Layer w0.13: v2(45.925,54.175) U28.H13@46.25,54.5
LCD_CTP_RST: CN4.7 U28.H14 | length 35.7
  Top Layer w0.12: v1(44.925,84.55) CN4.7@46.725,84.55
  Signal Layer 2 w0.1: 44.23,65.625 44.23,55.22 v2(45.275,54.175)
  Signal Layer 2 w0.12: 44.23,65.625 44.23,65.855 46.725,68.35 46.725,84.2 46.375,84.55 v1(44.925,84.55)
  Bottom Layer w0.13: v2(45.275,54.175) U28.H14@45.6,54.5
LCD_D0: CN7.18 U28.K13 | length 65
  Top Layer w0.13: CN7.18@24.94,20.175 24.855,20.26 24.855,20.445 23.875,21.425 18.549,21.425 17.21,22.765 17.21,26.21 21.44,30.44 21.44,37.095 29.34,44.995 32.167,44.995 34.797,42.365 36.4,42.365 41.66,42.365 42.4,41.625 42.525,41.5 v1(43.625,41.5)
  Signal Layer 2 w0.1: v1(43.625,41.5) 43.625,51.05 45.5,52.925 v2(45.975,52.925)
  Bottom Layer w0.13: v2@45.925,52.875 v2(45.975,52.925) U28.K13@46.25,53.2
LCD_D1: CN7.17 U28.J13 | length 51.8
  Top Layer w0.13: CN7.17@25.24,23.05 25.24,24.265 23.71,25.795 23.71,36.137 28.778,41.205 32.945,41.205 33.685,40.465 37.347,40.465 37.643,40.168 37.972,39.84 42.385,39.84 v1(42.8,39.425)
  Signal Layer 2 w0.1: v1(42.8,39.425) 42.797,39.425 42.675,39.547 42.8,39.672 42.8,41.625 42.8,43.825 43.3,44.325 43.3,51.275 45.55,53.525 v2(45.925,53.525)
  Bottom Layer w0.13: v2(45.925,53.525) U28.J13@46.25,53.85
LCD_D2: CN7.16 U28.B12 | length 79.4
  Top Layer w0.13: CN7.16@25.54,20.175 25.54,20.35 25.455,20.435 25.44,20.435 24.07,21.805 18.707,21.805 17.59,22.922 17.59,26.052 21.82,30.282 21.82,36.938 29.497,44.615 32.01,44.615 34.64,41.985 38.075,41.985 38.31,41.75 v1(40.5,41.75)
  Signal Layer 2 w0.1: v1(40.5,41.75) 40.5,42.7 40.4,42.8 40.4,45.65 41.475,46.725 41.475,57.65 41.375,57.75 41.375,63.55 v1(41.825,64)
  Bottom Layer w0.13: v1(41.825,64) 42.265,63.56 42.265,62.71 42.598,62.377 43.871,62.377 46.598,59.65 46.6,59.65 46.6,58.7 U28.B12@46.9,58.4
LCD_D3: CN7.15 U28.A13 | length 63.4
  Top Layer w0.13: CN7.15@25.84,23.05 25.84,24.203 24.09,25.953 24.09,35.979 28.196,40.085 37.19,40.085 37.875,39.4 v1(41.25,39.4)
  Signal Layer 2 w0.1: v1(41.25,39.4) 41.25,45.2 41.825,45.775 v1(41.825,63)
  Bottom Layer w0.13: v1(41.825,63) 41.825,62.5 42.178,62.147 43.775,62.147 45.729,60.194 46.25,59.672 U28.A13@46.25,59.05
LCD_D4: CN7.14 U28.R9 | length 63.5
  Top Layer w0.13: CN7.14@26.14,20.175 26.055,20.26 26.055,20.445 24.315,22.185 21.722,22.185 21.305,22.602 21.305,23.395 21.225,23.475 18.275,23.475 17.97,23.78 17.97,25.895 22.2,30.125 22.2,36.78 28.81,43.39 32.66,43.39 34.445,41.605 37.819,41.605 38.154,41.27 42.217,41.27 42.437,41.05 v1(47.65,41.05)
  Bottom Layer w0.13: v1(47.65,41.05) 47.65,41.625 47.65,42.1 48.395,42.845 48.395,48.919 48.85,49.374 U28.R9@48.85,49.95
LCD_D5: CN7.13 U28.P9 | length 51
  Top Layer w0.13: CN7.13@26.44,23.05 26.44,24.14 24.47,26.11 24.47,35.822 28.353,39.705 37.032,39.705 37.269,39.469 37.787,38.95 44.89,38.95 45.53,39.59 v1(48.115,39.59)
  Bottom Layer w0.13: v1(48.115,39.59) 48.115,41.965 48.625,42.475 48.625,48.824 49.175,49.374 49.175,50.275 U28.P9@48.85,50.6
LCD_D6: CN7.12 U28.N9 | length 55.6
  Top Layer w0.13: CN7.12@26.74,20.175 26.74,21.015 27.86,22.135 31.008,22.135 31.105,22.232 31.105,23.453 26.75,27.808 26.75,34.878 28.712,36.84 45.489,36.84 45.699,37.05 v1(45.775,37.05)
  Signal Layer 2 w0.1: v1(45.775,37.05) 46.325,37.6 46.325,48.075 48.525,50.275 v2(48.525,50.925)
  Bottom Layer w0.13: v2(48.525,50.925) U28.N9@48.85,51.25
LCD_D7: CN7.11 U28.R10 | length 48.9
  Top Layer w0.13: CN7.11@27.04,23.05 27.04,24.077 24.85,26.267 24.85,35.665 28.51,39.325 36.875,39.325 37.63,38.57 45.048,38.57 45.628,39.15 v1(46.75,39.15)
  Bottom Layer w0.13: v1(46.75,39.15) 46.75,41.899 47.935,43.084 47.935,49.11 48.2,49.375 U28.R10@48.2,49.95
LCD_D8: CN7.10 U28.P10 | length 55.1
  Top Layer w0.13: CN7.10@27.34,20.175 27.34,21.078 28.018,21.755 31.166,21.755 31.485,22.075 31.485,23.61 27.13,27.965 27.13,34.72 28.87,36.46 45.835,36.46 46.15,36.775 v1(46.725,36.775)
  Bottom Layer w0.13: v1(46.725,36.775) 47.19,37.24 47.19,41.625 47.19,41.965 48.165,42.94 48.165,49.015 48.525,49.375 48.525,50.275 U28.P10@48.2,50.6
LCD_D9: CN7.9 U28.R11 | length 47.9
  Top Layer w0.13: CN7.9@27.64,23.05 27.64,24.015 25.23,26.425 25.23,35.507 28.668,38.945 36.717,38.945 37.472,38.19 45.29,38.19 v1(45.625,38.525)
  Bottom Layer w0.13: v1(45.625,38.525) 45.625,41.725 47.475,43.575 47.475,49.843 47.55,49.918 U28.R11@47.55,49.95
LCD_D10: CN7.8 U28.P11 | length 54.2
  Top Layer w0.13: CN7.8@27.94,20.175 27.94,20.94 28.375,21.375 31.323,21.375 31.865,21.917 31.865,23.767 27.51,28.122 27.51,34.563 29.027,36.08 41.132,36.08 41.137,36.075 v1(46.225,36.075)
  Bottom Layer w0.13: v1(46.225,36.075) 46.225,41.625 46.225,41.7 47.705,43.18 47.705,49.28 47.875,49.45 47.875,50.275 U28.P11@47.55,50.6
LCD_D11: CN7.7 U28.N10 | length 49.5
  Top Layer w0.13: CN7.7@28.24,23.05 28.24,23.952 25.61,26.582 25.61,35.35 28.825,38.565 36.56,38.565 37.385,37.74 v1@45.175,37.74 ; v1(45.175,37.75) v1@45.33,37.75
  Signal Layer 2 w0.1: v1(45.175,37.75) 45.175,44.2 46.025,45.05 46.025,48.325 47.875,50.175 v2(47.875,50.925)
  Bottom Layer w0.13: v2(47.875,50.925) U28.N10@48.2,51.25
LCD_D12: CN7.6 U28.N11 | length 53.6
  Top Layer w0.13: CN7.6@28.54,20.175 28.54,20.665 28.87,20.995 31.481,20.995 32.245,21.76 32.245,23.925 27.89,28.28 27.89,34.405 29.185,35.7 40.975,35.7 41.05,35.625 v1(44.925,35.625)
  Signal Layer 2 w0.1: v1(44.925,35.625) 44.925,35.734 44.75,35.909 44.75,41.625 44.75,44.1 45.75,45.1 45.75,49.45 46.575,50.275 v2(47.225,50.925)
  Bottom Layer w0.13: v2(47.225,50.925) U28.N11@47.55,51.25
LCD_D13: CN7.5 U28.M15 | length 44.7
  Top Layer w0.13: CN7.5@28.84,23.05 28.84,23.89 25.99,26.74 25.99,35.192 28.398,37.6 33.975,37.6 v1(34.2,37.825)
  Bottom Layer w0.1: 36.4,49.4 37.025,50.025 38.15,50.025
  Bottom Layer w0.13: v1(34.2,37.825) 34.2,39.075 35.375,40.25 35.375,48.375 36.4,49.4 ; 38.15,50.025 41.225,50.025 43.1,51.9 U28.M15@44.95,51.9
LCD_D14: CN7.4 U28.L13 | length 54
  Top Layer w0.13: CN7.4@29.14,20.175 29.225,20.09 29.225,19.875 29.575,19.525 31.071,19.525 32.995,21.449 32.995,24.235 28.64,28.59 28.64,33.9 28.99,34.25 35.975,34.25 36.525,34.8 v1(44.4,34.8)
  Signal Layer 2 w0.1: v1(44.4,34.8) 44.4,50.7 v2(45.925,52.225)
  Bottom Layer w0.13: v2(45.925,52.225) U28.L13@46.25,52.55
LCD_D15: CN7.3 U28.K12 | length 49
  Top Layer w0.13: CN7.3@29.44,23.05 29.44,23.827 26.37,26.897 26.37,35.035 28.555,37.22 43.095,37.22 43.175,37.3 v1(43.675,37.3)
  Signal Layer 2 w0.1: v1(43.675,37.3) 44.05,37.675 44.05,41.625 44.05,50.845 45.78,52.575 46.275,52.575 v2(46.575,52.875)
  Bottom Layer w0.13: v2(46.575,52.875) U28.K12@46.9,53.2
